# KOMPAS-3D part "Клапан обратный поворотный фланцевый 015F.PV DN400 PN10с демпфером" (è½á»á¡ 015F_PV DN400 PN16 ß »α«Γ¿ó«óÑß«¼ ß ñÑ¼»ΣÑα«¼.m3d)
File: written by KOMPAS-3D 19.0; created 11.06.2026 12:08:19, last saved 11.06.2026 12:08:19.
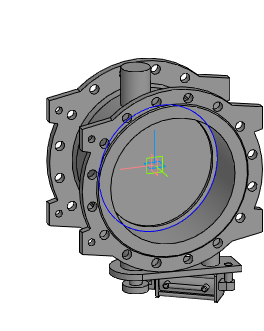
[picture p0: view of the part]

Document properties: Автор: Энергия; Полное имя файла: Z:\3.Личные\kachalov\001_3d для проектировщиков\5.5 Тип 015F.PV Клапан обратный поворотный с двумя эксцентриками\_stp_Клапан 015F.PV DN300-DN1200 с противовесом с демпфером\Клапан 015F_PV DN400 PN16 с противовесом с демпфером.m3d

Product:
- Part/product: Клапан обратный поворотный фланцевый 015F.PV DN400 PN10с демпфером

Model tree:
1. Операция без истории:1
2. Сплайн:1
     Координата Y = 30; Координата Z = 200; Вес = 1; Координата X = 400; Координата Y = 82.661; Координата Z = 200; Вес = 0.333333; Координата X = 400; Координата Y = 82.661; Координата Z = -200; Вес = 0.333333; Координата Y = 30; Координата Z = -200; Вес = 1; Координата X = -400; Координата Y = -22.661; Координата Z = -200; Вес = 0.333333; Координата X = -400; Координата Y = -22.661; Координата Z = 200; Вес = 0.333333; Порядок = 4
